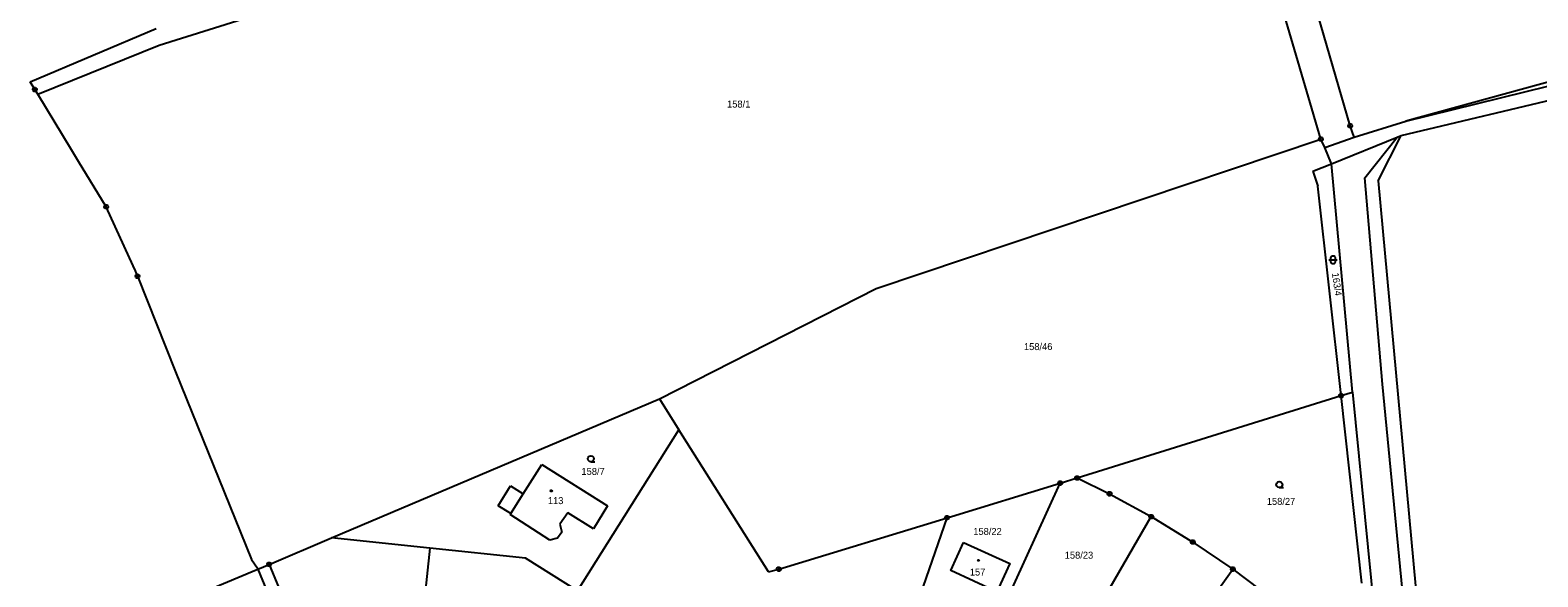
# Model space of a CAD drawing. Extents: x -779723 to -777378, y -1011169 to -1009297.
# Drawn here: x -779564.1 to -779195.8, y -1010014.1 to -1009880.5 of the extents above; entities that cross this region are included whole.
import ezdxf

# ---------------------------------------------------------------- set-up
doc = ezdxf.new("R2010")
doc.units = 0
for name, color, linetype in [('Default', 7, 'Continuous'), ('KN_HRANICE', 7, 'Continuous'), ('KN_KULTURY', 7, 'Continuous'), ('KN_PARCELY', 7, 'Continuous'), ('KN_SLUCKY', 7, 'Continuous')]:
    doc.layers.add(name, color=color, linetype=linetype)

# ---------------------------------------------------------------- blocks, each defined once
blk = doc.blocks.new('304')
at = {"layer": 'Default'}
blk.add_lwpolyline([(0, 0), (-0.38, 0.1), (-0.65, 0.37), (-0.75, 0.74), (-0.65, 1.11), (-0.38, 1.38), (-0.01, 1.48), (0.36, 1.38), (0.63, 1.11), (0.73, 0.73), (0.63, 0.35), (0.36, 0.08), (-0.02, -0.02), (0.98, -0.02)], dxfattribs=at)
blk = doc.blocks.new('316')
at = {"layer": 'Default'}
for points in [[(-1, 1), (0.27, 1), (1, 1)], [(-0.5, 1.5), (-0.4, 1.79), (-0.15, 1.97), (0.16, 1.97), (0.41, 1.79), (0.51, 1.5), (0.51, 0.5), (0.41, 0.21), (0.16, 0.03), (-0.15, 0.03), (-0.4, 0.21), (-0.5, 0.5), (-0.5, 1.5)]]:
    blk.add_lwpolyline(points, dxfattribs=at)
blk = doc.blocks.new('105')
at = {"layer": 'Default'}
blk.add_line((-0.12, 0), (0.12, 0), dxfattribs=at)
blk.add_lwpolyline([(0.15, 0.48), (0.4, 0.3), (0.5, 0.01), (0.4, -0.28), (0.15, -0.46), (-0.16, -0.46), (-0.41, -0.28), (-0.51, 0.01), (-0.41, 0.3), (-0.16, 0.48), (0.15, 0.48)], dxfattribs=at)
blk = doc.blocks.new('402')
at = {"layer": 'Default'}
blk.add_lwpolyline([(0.09, 0.15), (0.18, 0), (0.09, -0.15), (-0.09, -0.15), (-0.18, 0), (-0.09, 0.15), (0.09, 0.15)], dxfattribs=at)

msp = doc.modelspace()

# ---------------------------------------------------------------- linework, layer by layer
at = {"layer": 'KN_HRANICE'}
for p, q in [((-779241.62, -1009903.83), (-779272.7, -1009797.05)), ((-779248.82, -1009907.09), (-779278.74, -1009805.06)), ((-779532.56, -1009884.15), (-779506.87, -1009876.1)), ((-779564.1, -1009893.09), (-779533.32, -1009880.08)), ((-779562.25, -1009896.12), (-779532.56, -1009884.15)), ((-779161.05, -1009884.21), (-779228.01, -1009902.71)), ((-779228.01, -1009902.71), (-779160.94, -1009886.18)), ((-779229.16, -1009906.17), (-779157.23, -1009889.11)), ((-779562.94, -1009894.99), (-779564.1, -1009893.09)), ((-779562.25, -1009896.12), (-779562.94, -1009894.99)), ((-779553.96, -1009909.75), (-779562.25, -1009896.12)), ((-779240.66, -1009906.64), (-779228.01, -1009902.71)), ((-779246.23, -1009913.12), (-779230.18, -1009906.58)), ((-779240.66, -1009906.64), (-779241.62, -1009903.83)), ((-779238.1, -1009916.55), (-779230.18, -1009906.58)), ((-779234.8, -1009917.25), (-779229.16, -1009906.17)), ((-779230.18, -1009906.58), (-779229.16, -1009906.17)), ((-779552.25, -1009912.56), (-779553.96, -1009909.75)), ((-779357.43, -1009943.56), (-779248.82, -1009907.09)), ((-779247.8, -1009909.13), (-779248.82, -1009907.09)), ((-779247.8, -1009909.13), (-779240.66, -1009906.64)), ((-779246.23, -1009913.12), (-779247.8, -1009909.13)), ((-779545.52, -1009923.61), (-779552.25, -1009912.56)), ((-779250.74, -1009914.96), (-779246.23, -1009913.12)), ((-779241.08, -1009968.91), (-779246.23, -1009913.12)), ((-779250.74, -1009914.96), (-779249.52, -1009918.58)), ((-779233.71, -1009966.95), (-779238.1, -1009916.55)), ((-779234.8, -1009917.25), (-779223.59, -1010039.03)), ((-779243.85, -1009969.77), (-779249.52, -1009918.58)), ((-779538.94, -1009938.03), (-779545.52, -1009923.61)), ((-779538.37, -1009939.28), (-779538.94, -1009938.03)), ((-779537.89, -1009940.61), (-779538.37, -1009939.28)), ((-779537.89, -1009940.61), (-779528.57, -1009963.94)), ((-779410.38, -1009970.58), (-779357.43, -1009943.56)), ((-779528.57, -1009963.94), (-779510, -1010009.82)), ((-779243.85, -1009969.77), (-779241.08, -1009968.91)), ((-779241.08, -1009968.91), (-779234.07, -1010040.11)), ((-779226.79, -1010039.25), (-779233.71, -1009966.95)), ((-779490.5, -1010004.56), (-779410.38, -1009970.58)), ((-779410.38, -1009970.58), (-779405.63, -1009978.11)), ((-779308.35, -1009989.9), (-779243.85, -1009969.77)), ((-779238.78, -1010015.64), (-779243.85, -1009969.77)), ((-779430.36, -1010017.45), (-779405.63, -1009978.11)), ((-779383.71, -1010012.84), (-779405.63, -1009978.11)), ((-779443.63, -1009993.74), (-779439.14, -1009986.62)), ((-779439.14, -1009986.62), (-779423.07, -1009996.75)), ((-779340.12, -1009999.61), (-779312.49, -1009991.16)), ((-779326.85, -1010022.6), (-779312.49, -1009991.16)), ((-779312.49, -1009991.16), (-779308.35, -1009989.9)), ((-779308.35, -1009989.9), (-779300.4, -1009993.78)), ((-779449.77, -1009996.67), (-779446.72, -1009991.8)), ((-779446.72, -1009991.8), (-779443.63, -1009993.74)), ((-779300.4, -1009993.78), (-779290.22, -1009999.35)), ((-779446.7, -1009998.61), (-779449.77, -1009996.67)), ((-779446.86, -1009998.86), (-779446.7, -1009998.61)), ((-779432.77, -1009998.38), (-779434.71, -1010001.23)), ((-779426.49, -1010002.32), (-779432.77, -1009998.38)), ((-779423.07, -1009996.75), (-779426.49, -1010002.32)), ((-779437.12, -1010005.06), (-779446.86, -1009998.86)), ((-779434.71, -1010001.23), (-779434.23, -1010003.15)), ((-779381.24, -1010012.19), (-779340.12, -1009999.61)), ((-779345.89, -1010016.32), (-779340.12, -1009999.61)), ((-779309, -1010031.79), (-779290.22, -1009999.35)), ((-779290.22, -1009999.35), (-779280.07, -1010005.56)), ((-779505.72, -1010011.01), (-779490.5, -1010004.56)), ((-779466.49, -1010007.04), (-779490.5, -1010004.56)), ((-779435.26, -1010004.63), (-779437.12, -1010005.06)), ((-779434.23, -1010003.15), (-779435.26, -1010004.63)), ((-779280.07, -1010005.56), (-779270.32, -1010012.18)), ((-779466.49, -1010007.04), (-779471.6, -1010056.37)), ((-779443.07, -1010009.46), (-779466.49, -1010007.04)), ((-779430.36, -1010017.45), (-779443.07, -1010009.46)), ((-779522.9, -1010018.23), (-779509.9, -1010012.78)), ((-779510, -1010009.82), (-779508.57, -1010011.97)), ((-779509.9, -1010012.78), (-779508.48, -1010012.18)), ((-779508.57, -1010011.97), (-779508.48, -1010012.18)), ((-779508.48, -1010012.18), (-779505.72, -1010011.01)), ((-779508.48, -1010012.18), (-779489.42, -1010058.31)), ((-779505.72, -1010011.01), (-779486.32, -1010057.97)), ((-779383.71, -1010012.84), (-779381.24, -1010012.19)), ((-779292.64, -1010043.39), (-779270.32, -1010012.18)), ((-779270.32, -1010012.18), (-779260.26, -1010019.77))]:
    msp.add_line(p, q, dxfattribs=at)
msp.add_lwpolyline([(-779336.09, -1010005.63), (-779324.79, -1010010.8), (-779327.97, -1010017.71), (-779339.22, -1010012.55)], close=True, dxfattribs=at)
at = {"layer": 'KN_SLUCKY'}
msp.add_line((-779446.7, -1009998.61), (-779443.63, -1009993.74), dxfattribs=at)

# ---------------------------------------------------------------- block references
at = {"layer": 'KN_KULTURY'}
for name, p in [('316', (-779245.83, -1009937.58)), ('304', (-779427.12, -1009985.94)), ('304', (-779258.94, -1009992.24)), ('402', (-779436.78, -1009993.04)), ('402', (-779332.44, -1010010.02))]:
    msp.add_blockref(name, p, dxfattribs=at)
at = {"layer": 'KN_PARCELY'}
for p in [(-779562.94, -1009894.99), (-779248.82, -1009907.09), (-779241.62, -1009903.83), (-779545.52, -1009923.61), (-779537.89, -1009940.61), (-779243.85, -1009969.77), (-779312.49, -1009991.16), (-779308.35, -1009989.9), (-779300.4, -1009993.78), (-779340.12, -1009999.61), (-779290.22, -1009999.35), (-779280.07, -1010005.56), (-779505.72, -1010011.01), (-779381.24, -1010012.19), (-779270.32, -1010012.18)]:
    msp.add_blockref('105', p, dxfattribs=at)

# ---------------------------------------------------------------- texts
for s, p in [('158/1', (-779393.86, -1009899.38)), ('158/46', (-779321.33, -1009958.65)), ('158/7', (-779429.43, -1009989.15)), ('113', (-779437.64, -1009996.29)), ('158/27', (-779262.01, -1009996.47)), ('158/22', (-779333.71, -1010003.82)), ('158/23', (-779311.37, -1010009.62)), ('157', (-779334.56, -1010013.74))]:
    msp.add_text(s, height=1.7, dxfattribs=at).set_placement(p)
msp.add_text('163/4', height=1.7, rotation=277.999, dxfattribs=at).set_placement((-779246.12, -1009939.86))

doc.saveas('drawing.dxf')
